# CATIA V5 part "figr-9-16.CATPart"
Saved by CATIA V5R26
Part number: Part1
Bounding box of the stored display mesh (mm): x -77.304 to 77.304, y -77.304 to 125.507, z 0 to 125
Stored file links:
  D:\_Deepak\CATIA\CATIA V5-6R2016_Deepak\Resources\Part files\Partfiles\c09_catia_v5_6r2016_prt\figr-9-16.CATPart
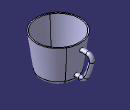
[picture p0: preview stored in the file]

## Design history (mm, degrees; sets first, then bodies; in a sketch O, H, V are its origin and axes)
Set1
  Plane1: type Normal, Curve Sketch3, RefPoint vertex of Sketch3
Body1 (main body)
  Sketch1 on yz-plane, origin (0, 0, 0), H (0, 1, 0), V (0, 0, 1)
    line L1 (0, 0) -> (60, 0)
    point P1 (60, 0)
    point P2 (60, 0)
    line L2 (60, 0) -> (77.5, 125)
    point P3 (77.5, 125)
    line L3 (77.5, 125) -> (0, 125)
    point P4 (0, 125)
    line L4 (0, 125) -> (0, 0)
    axis line L5 (0, 150.2858) -> (0, -31.0593)
    point P5 (0, 150.2858)
    radius about axis P1 L5 = 60
    radius about axis P3 L5 = 77.5
    distance L3 L1 = 125
    horizontal: L1 H, L3 H
    coincidence: P4 V, P2 P1, P5 V
    vertical: L4 V, L5 V
  Shaft1: profile Sketch1, axis Sketch1.L5, angle 360
  Fillet1: radius 15, on edge [face of Shaft1 | face of Shaft1]
  Shell1: ExtOffset 0, Face face of Shaft1, IntOffset 4
  Sketch2 on Plane1, origin (0, 62.9841, 0), H (-1, 0, 0), V (0, 0, 1)
    circle A1 centre (0, 22.002) radius 7.5
    reference projected point E1 (0, 22.002) from vertex of Sketch3
    radius A1 = 7.5
    concentricity: A1 E1
  Sketch3 on yz-plane, origin (0, 0, 0), H (0, 1, 0), V (0, 0, 1)
    line L1 (62.9841, 22.002) -> (78.2172, 22.002)
    arc A1 centre (78.2172, 44.1133) radius 22.1113 from (78.2172, 22.002) to (97.9307, 34.0988) ccw
    arc A2 centre (-112.3295, 140.9107) radius 235.8349 from (97.9307, 34.0988) to (117.8681, 89.6549) ccw
    arc A3 centre (104.0328, 92.7355) radius 14.1742 from (117.8681, 89.6549) to (104.4272, 106.9041) ccw
    arc A4 centre (93.6744, -279.4123) radius 386.4661 from (104.4272, 106.9041) to (82.9216, 106.9041) ccw
    horizontal: L1 H
    tangency: A1 L1, A2 A1, A3 A2, A4 A3
  Rib1: profile Sketch2, centre curve Sketch3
